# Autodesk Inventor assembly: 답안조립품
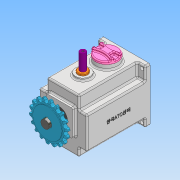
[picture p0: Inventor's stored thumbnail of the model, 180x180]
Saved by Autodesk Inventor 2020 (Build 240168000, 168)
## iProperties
Created: 2022-01
Part Number: 답안조립품
Document SubType Name: Assembly
Designer: user
Author: user
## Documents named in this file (16)
- C:\Users\user\Desktop\720112V1007\답안조립품.iam
- C:\Users\user\Desktop\720112V1007\멈춤나사 M3.ipt
- C:\Users\user\Desktop\720112V1007\메인 축.ipt
- C:\Users\user\Desktop\720112V1007\베어링 608.ipt
- C:\Users\user\Desktop\720112V1007\베어링 6003.ipt
- C:\Users\user\Desktop\720112V1007\본체.ipt
- C:\Users\user\Desktop\720112V1007\볼트 M4 x 10.ipt
- C:\Users\user\Desktop\720112V1007\부시.ipt
- C:\Users\user\Desktop\720112V1007\상부 캡.ipt
- C:\Users\user\Desktop\720112V1007\서브 축.ipt
- C:\Users\user\Desktop\720112V1007\스프로킷.ipt
- C:\Users\user\Desktop\720112V1007\슬라이더.ipt
- C:\Users\user\Desktop\720112V1007\오일 실 8 x 22 x 7.ipt
- C:\Users\user\Desktop\720112V1007\오일 실 17 x 32 x 8.ipt
- C:\Users\user\Desktop\720112V1007\커버.ipt
- C:\Users\user\Desktop\720112V1007\키 5 x 5.ipt
